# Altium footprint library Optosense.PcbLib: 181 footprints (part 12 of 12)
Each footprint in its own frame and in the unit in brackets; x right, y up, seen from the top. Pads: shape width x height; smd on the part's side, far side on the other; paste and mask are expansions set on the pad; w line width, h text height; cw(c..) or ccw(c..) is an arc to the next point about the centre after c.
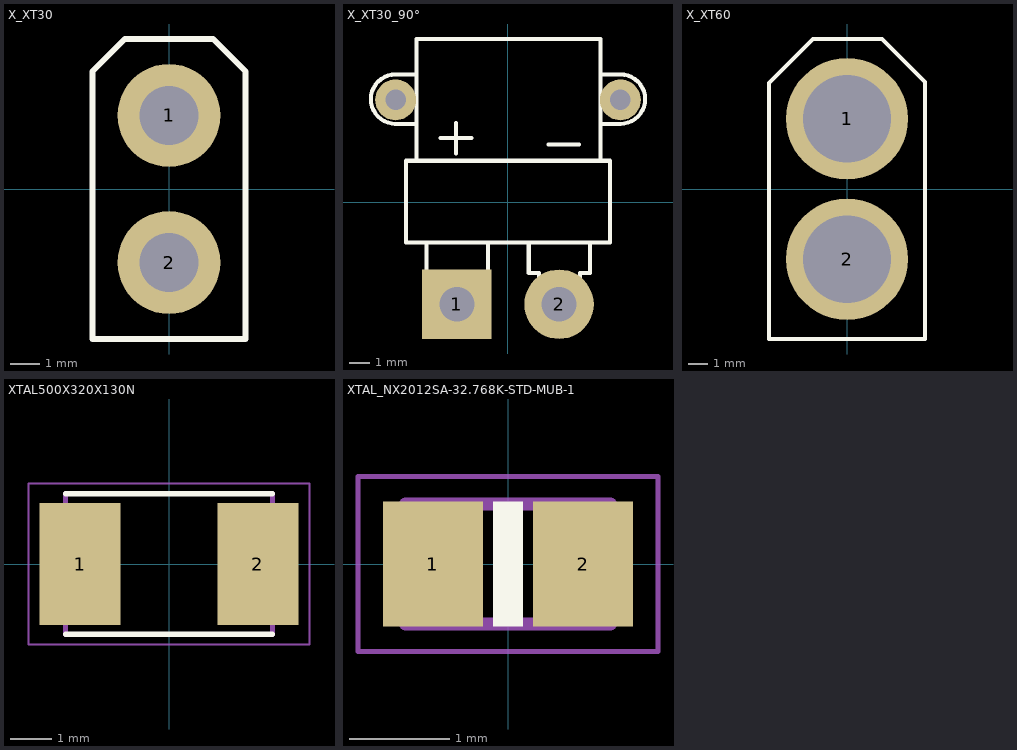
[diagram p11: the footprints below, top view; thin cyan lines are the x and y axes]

## X_XT30 [mm] "XT30PB-M"
pads (2):
  round 3.5 hole 2: 1(0,2.5) 2(0,-2.5)
Top Overlay:
  lines w0.2: -2.6,-5.1 -2.6,4 -1.5,5.1 1.5,5.1 2.6,4 2.6,-5.1 -2.6,-5.1
3D body "User Library-XT30.step": height 12.6, standoff -2.9, extent -2.6,-5.2 2.7,5.2

## X_XT30_90° [mm]
pads (4):
  rect 3.4x3.4 hole 1.7: 1(-2.5,-5)
  round 3.4 hole 1.7: 2(2.5,-5)
  round 2 hole 1: ""(-5.5,5) ""(5.5,5)
Top Overlay:
  lines w0.2: -5.52,3.83 -4.543,3.83 ; -5.5,3.827 cw(c-5.5,5.037) -5.5,6.246 -4.523,6.246 ; -4.483,2.044 -4.483,7.979 4.517,7.979 4.517,2.062 ; -3.983,-2.078 -3.983,-3.468 -3.483,-3.468 ; -3.483,-3.521 -3.483,-5.921 -1.483,-5.921 -1.483,-3.521 ; -3.295,3.127 -2.545,3.127 ; -2.545,2.377 -2.545,3.127 ; -2.545,3.877 -2.545,3.127 ; -1.795,3.127 -2.545,3.127 ; -1.483,-3.468 -0.983,-3.468 -0.983,-2.078 ; 1.017,-2.078 1.017,-3.468 1.517,-3.468 1.517,-5.868 ; 1.978,2.81 2.728,2.81 3.478,2.81 ; 3.517,-5.868 3.517,-3.468 4.017,-3.468 4.017,-2.078 ; 4.551,3.825 5.471,3.825 ; 4.551,6.246 5.5,6.246 cw(c5.5,5.037) 5.5,3.827 ; -5,-1.978 -5,2.022 5,2.022 5,-1.978 -5,-1.978
3D body "User Library-XT30PW-M.step": height 5, standoff -2, extent -6.65,-6 6.65,7.95

## X_XT60 [mm]
pads (2):
  round 6.25 hole 4.5: 1(0,3.6) 2(0,-3.6)
Top Overlay:
  lines w0.2: -4,-7.7 -4,5.45 -1.75,7.7 1.8,7.7 4,5.5 4,-7.7 -4,-7.7

## XTAL500X320X130N [mm]
pads (2):
  rect 1.95x2.95 smd: 1(-2.15,0) 2(2.15,0)
Top Overlay:
  lines w0.127: -2.5,-1.7 2.5,-1.7 ; -2.5,1.7 2.5,1.7
Mechanical 13:
  lines w0.127: -2.5,-1.7 -2.5,1.7 ; 2.5,-1.7 2.5,1.7
Mechanical 15:
  lines w0.05: -3.4,-1.95 -3.4,1.95 3.4,1.95 3.4,-1.95 -3.4,-1.95
3D body "ABM3-24.000MHZ-B2-T.STEP": height 1.3, standoff 0, extent -2.502,-1.651 2.502,1.651

## XTAL_NX2012SA-32.768K-STD-MUB-1 [mm]
pads (2):
  rect 1x1.25 smd: 1(-0.75,0) 2(0.75,0)
Top Overlay:
  rectangle: -0.15,-0.625 0.15,0.625
Mechanical 13:
  lines w0.127: -1.025,-0.6 1.025,-0.6 1.025,0.6 -1.025,0.6 -1.025,-0.6
Mechanical 15:
  lines w0.05: -1.5,-0.875 1.5,-0.875 1.5,0.875 -1.5,0.875 -1.5,-0.875
3D body: height 0.55, standoff 0.05, extent -1.1,-0.6 1.1,0.6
